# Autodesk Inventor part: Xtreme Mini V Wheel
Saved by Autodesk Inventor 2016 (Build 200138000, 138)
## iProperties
Created: 2015-11
Part Number: Xtreme Mini V Wheel
Material: Generic
Document SubType Name: Modeling
Designer: John
Density: 1 g/cm^3
Appearance: Default
Author: John
Revision Number: ANY
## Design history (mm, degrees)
feature "Revolve1"
body "Solid1"
